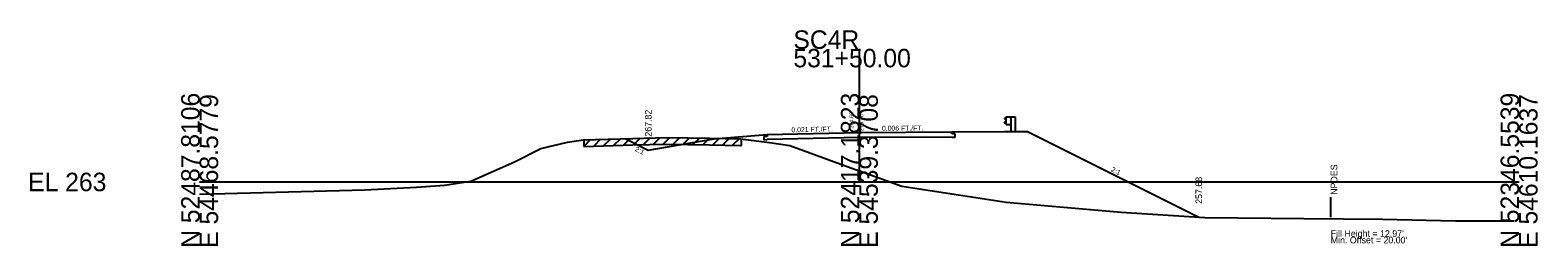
# Model space of a CAD drawing. Extents: x 7498 to 13027, y 90095 to 109625.
# Drawn here: x 9498.3 to 9726.8, y 101595.5 to 101628.2 of the extents above; entities that cross this region are included whole.
import ezdxf

# ---------------------------------------------------------------- set-up
doc = ezdxf.new("R2010")
doc.units = 0
for name, color, linetype in [('Level 10', 7, 'Continuous'), ('Level 11', 7, 'Continuous'), ('Level 12', 7, 'Continuous'), ('Level 24', 7, 'Continuous'), ('Level 32', 7, 'Continuous'), ('Level 33', 7, 'Continuous'), ('Level 50', 7, 'Continuous'), ('Level 55', 7, 'Continuous'), ('Level 59', 7, 'Continuous'), ('Level 6', 7, 'Continuous'), ('Level 60', 7, 'Continuous'), ('Level 61', 7, 'Continuous'), ('Level 63', 7, 'Continuous'), ('Level 7', 7, 'Continuous')]:
    doc.layers.add(name, color=color, linetype=linetype)

msp = doc.modelspace()

# ---------------------------------------------------------------- linework, layer by layer
at = {"layer": 'Level 11'}
for p, q in [((9609.99, 101612.07), (9609.49, 101612.05)), ((9609.49, 101612.05), (9609.49, 101611.57)), ((9609.49, 101611.57), (9609.99, 101611.59)), ((9609.99, 101612.37), (9609.99, 101612.07)), ((9637.99, 101612.44), (9637.99, 101612.74)), ((9638.49, 101612.45), (9637.99, 101612.44)), ((9637.99, 101611.96), (9638.49, 101611.97)), ((9638.49, 101611.97), (9638.49, 101612.45))]:
    msp.add_line(p, q, dxfattribs=at)
at = {"layer": 'Level 12'}
for p, q in [((9623.99, 101611.88), (9609.99, 101611.59)), ((9637.99, 101611.96), (9623.99, 101611.88))]:
    msp.add_line(p, q, dxfattribs=at)
at = {"layer": 'Level 24'}
for p, q in [((9646.26, 101614.97), (9645.99, 101614.77)), ((9645.99, 101614.77), (9645.99, 101614.72)), ((9645.99, 101614.72), (9646.26, 101614.52)), ((9645.99, 101614.2), (9646.26, 101614.4)), ((9645.99, 101614.15), (9645.99, 101614.2)), ((9646.26, 101613.95), (9645.99, 101614.15)), ((9646.26, 101613.88), (9646.26, 101615.04)), ((9646.26, 101615.04), (9646.93, 101615.04)), ((9646.26, 101613.88), (9646.93, 101613.88)), ((9646.93, 101615.04), (9646.93, 101612.8)), ((9646.93, 101615.04), (9647.6, 101615.04)), ((9647.6, 101615.04), (9647.6, 101612.8))]:
    msp.add_line(p, q, dxfattribs=at)
at = {"layer": 'Level 55'}
msp.add_line((9695.44, 101599.84), (9695.44, 101602.84), dxfattribs=at)
at = {"layer": 'Level 59'}
for p, q in [((9609.99, 101612.37), (9623.99, 101612.66)), ((9623.99, 101612.66), (9637.99, 101612.74))]:
    msp.add_line(p, q, dxfattribs=at)
at = {"layer": 'Level 6'}
for p, q in [((9601.99, 101611.7), (9609.99, 101612.37)), ((9637.99, 101612.74), (9645.99, 101612.79)), ((9645.99, 101612.79), (9649.49, 101612.81))]:
    msp.add_line(p, q, dxfattribs=at)
at = {"layer": 'Level 60'}
for p, q in [((9579.74, 101611.19), (9582.13, 101611.55)), ((9582.13, 101611.55), (9589.63, 101611.77)), ((9589.63, 101611.77), (9594.69, 101611.89)), ((9594.69, 101611.89), (9601.27, 101611.79)), ((9601.27, 101611.79), (9605.96, 101611.71)), ((9605.96, 101611.71), (9610.37, 101611.14)), ((9571.7, 101608.21), (9575.7, 101610.21)), ((9575.7, 101610.21), (9579.74, 101611.19)), ((9610.37, 101611.14), (9613.46, 101610.69)), ((9613.46, 101610.69), (9623.25, 101607.12)), ((9565.08, 101605.26), (9571.7, 101608.21)), ((9623.25, 101607.12), (9623.99, 101606.85)), ((9623.99, 101606.85), (9630.43, 101604.53)), ((9556.88, 101604.37), (9561.11, 101604.67)), ((9561.11, 101604.67), (9565.08, 101605.26)), ((9630.43, 101604.53), (9639.02, 101603.21)), ((9523.99, 101603.29), (9549.05, 101603.98)), ((9549.05, 101603.98), (9556.88, 101604.37)), ((9639.02, 101603.21), (9646.24, 101602.1)), ((9646.24, 101602.1), (9663.67, 101600.58)), ((9663.67, 101600.58), (9676.34, 101599.78)), ((9676.34, 101599.78), (9691.35, 101599.62)), ((9691.35, 101599.62), (9703.28, 101599.53)), ((9703.28, 101599.53), (9714.35, 101599.26)), ((9714.35, 101599.26), (9723.24, 101599.25))]:
    msp.add_line(p, q, dxfattribs=at)
at = {"layer": 'Level 61'}
for p, q in [((9583.26, 101611.58), (9582.23, 101610.55)), ((9582.23, 101611.55), (9582.23, 101610.55)), ((9584.76, 101611.63), (9583.73, 101610.6)), ((9586.26, 101611.67), (9585.23, 101610.64)), ((9587.77, 101611.71), (9586.73, 101610.68)), ((9589.27, 101611.76), (9588.24, 101610.73)), ((9590.77, 101611.79), (9589.74, 101610.77)), ((9592.27, 101611.83), (9591.24, 101610.8)), ((9593.77, 101611.86), (9592.75, 101610.84)), ((9595.25, 101611.88), (9594.25, 101610.88)), ((9596.74, 101611.86), (9595.75, 101610.87)), ((9598.24, 101611.84), (9597.25, 101610.85)), ((9599.74, 101611.81), (9598.76, 101610.83)), ((9601.25, 101611.79), (9600.26, 101610.81)), ((9602.75, 101611.77), (9601.76, 101610.78)), ((9604.25, 101611.74), (9603.26, 101610.76)), ((9605.75, 101611.71), (9604.77, 101610.73)), ((9606.12, 101610.69), (9606.12, 101611.69)), ((9582.23, 101610.55), (9589.63, 101610.77)), ((9589.63, 101610.77), (9594.69, 101610.89)), ((9594.69, 101610.89), (9601.27, 101610.79)), ((9601.27, 101610.79), (9605.96, 101610.71)), ((9605.96, 101610.71), (9606.12, 101610.69))]:
    msp.add_line(p, q, dxfattribs=at)
at = {"layer": 'Level 63'}
for p, q in [((9623.99, 101605.16), (9623.99, 101625.35)), ((9523.99, 101605.16), (9623.99, 101605.16)), ((9623.99, 101605.16), (9723.99, 101605.16))]:
    msp.add_line(p, q, dxfattribs=at)
at = {"layer": 'Level 7'}
for p, q in [((9588.47, 101611.73), (9591.99, 101609.97)), ((9591.99, 101609.97), (9601.99, 101611.7)), ((9649.49, 101612.81), (9675.44, 101599.84))]:
    msp.add_line(p, q, dxfattribs=at)

# ---------------------------------------------------------------- texts
at = {"layer": 'Level 10'}
msp.add_text('264.69', height=0.6, rotation=90, dxfattribs=at).set_placement((9623.08, 101613.25))
at = {"layer": 'Level 32'}
for s, rotation, p in [('0.021 FT./FT.', 1.1916, (9613.7, 101612.69)), ('0.006 FT./FT.', 0.356, (9627.42, 101612.93)), ('2:1', 333.435, (9589.89, 101609.89)), ('2:1', 333.435, (9662.07, 101606.8))]:
    msp.add_text(s, height=0.75, rotation=rotation, dxfattribs=at).set_placement(p)
at = {"layer": 'Level 33'}
for s, p in [('267.82', (9592.49, 101612.03)), ('257.68', (9675.94, 101601.84))]:
    msp.add_text(s, height=1, rotation=90, dxfattribs=at).set_placement(p)
at = {"layer": 'Level 50'}
msp.add_text(' NPDES', height=1, rotation=90, dxfattribs=at).set_placement((9696.44, 101602.84))
for s, p in [("Fill Height = 12.97' ", (9695.44, 101596.84)), ("Min. Offset = 20.00' ", (9695.44, 101595.84))]:
    msp.add_text(s, height=1, dxfattribs=at).set_placement(p)
at = {"layer": 'Level 59'}
msp.add_text(' 270.50', height=0.6, rotation=90, dxfattribs=at).set_placement((9624.59, 101612.66))
at = {"layer": 'Level 63'}
for s, p in [('SC4R', (9613.99, 101625.35)), ('531+50.00', (9613.99, 101622.55)), ('EL 263', (9497.99, 101603.76))]:
    msp.add_text(s, height=2.8, dxfattribs=at).set_placement(p)
for s, p in [('N 52487.8106', (9523.99, 101595.16)), ('E 54468.5779', (9526.79, 101595.16)), ('N 52417.1823', (9623.99, 101595.16)), ('E 54539.3708', (9626.79, 101595.16)), ('N 52346.5539', (9723.99, 101595.16)), ('E 54610.1637', (9726.79, 101595.16))]:
    msp.add_text(s, height=2.8, rotation=90, dxfattribs=at).set_placement(p)

doc.saveas('drawing.dxf')
